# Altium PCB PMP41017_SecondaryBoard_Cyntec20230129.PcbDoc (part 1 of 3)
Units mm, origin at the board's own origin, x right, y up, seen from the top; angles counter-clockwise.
Board outline 56.93 x 50 mm, 6 copper layers (Top Layer, Layer 1, Layer 3, Layer 4, Layer 2, Bottom Layer), stack 1.219 mm thick; 147 components, 63 nets, 876 pads, 1174 vias.
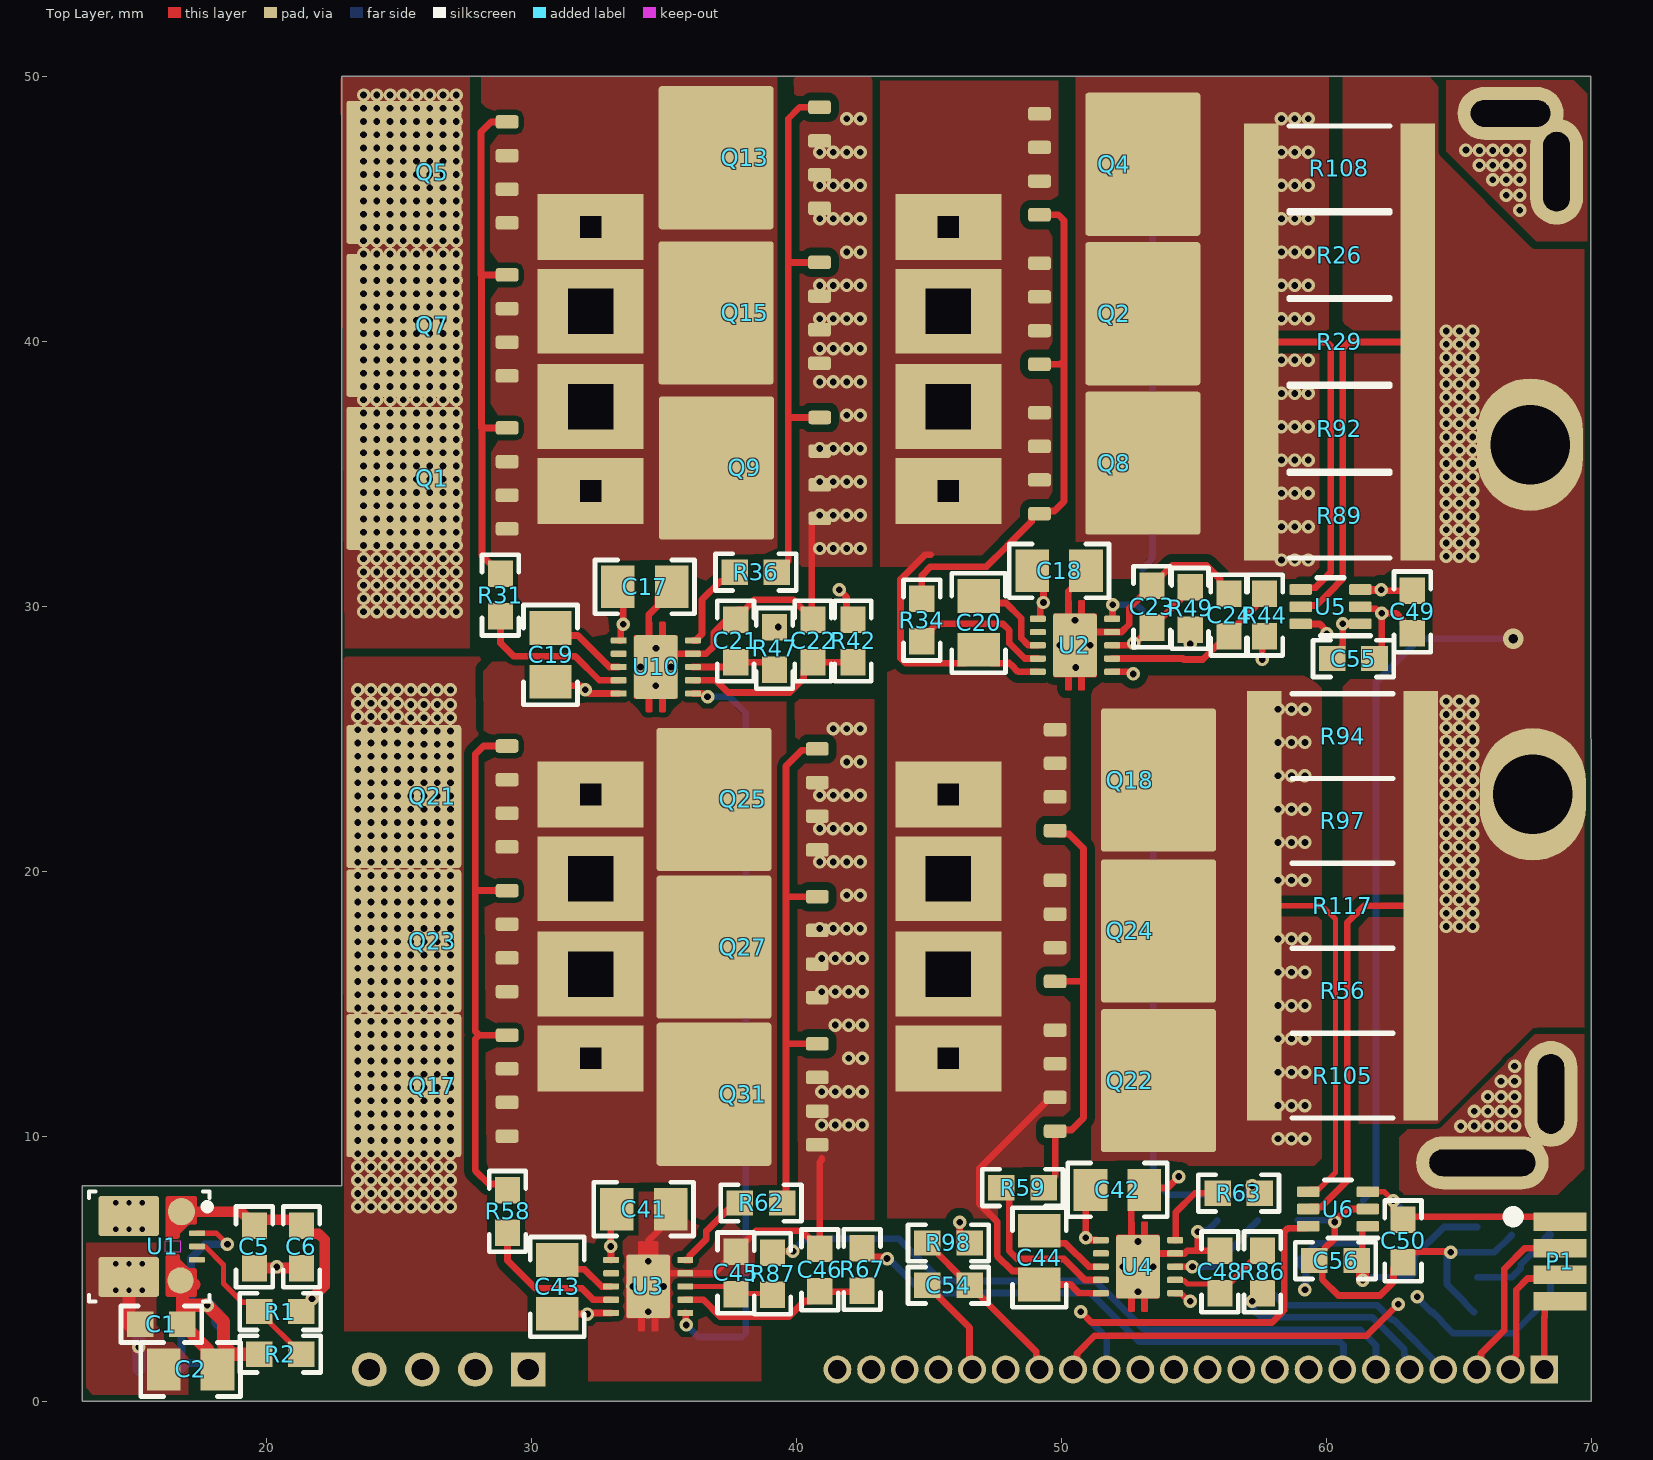
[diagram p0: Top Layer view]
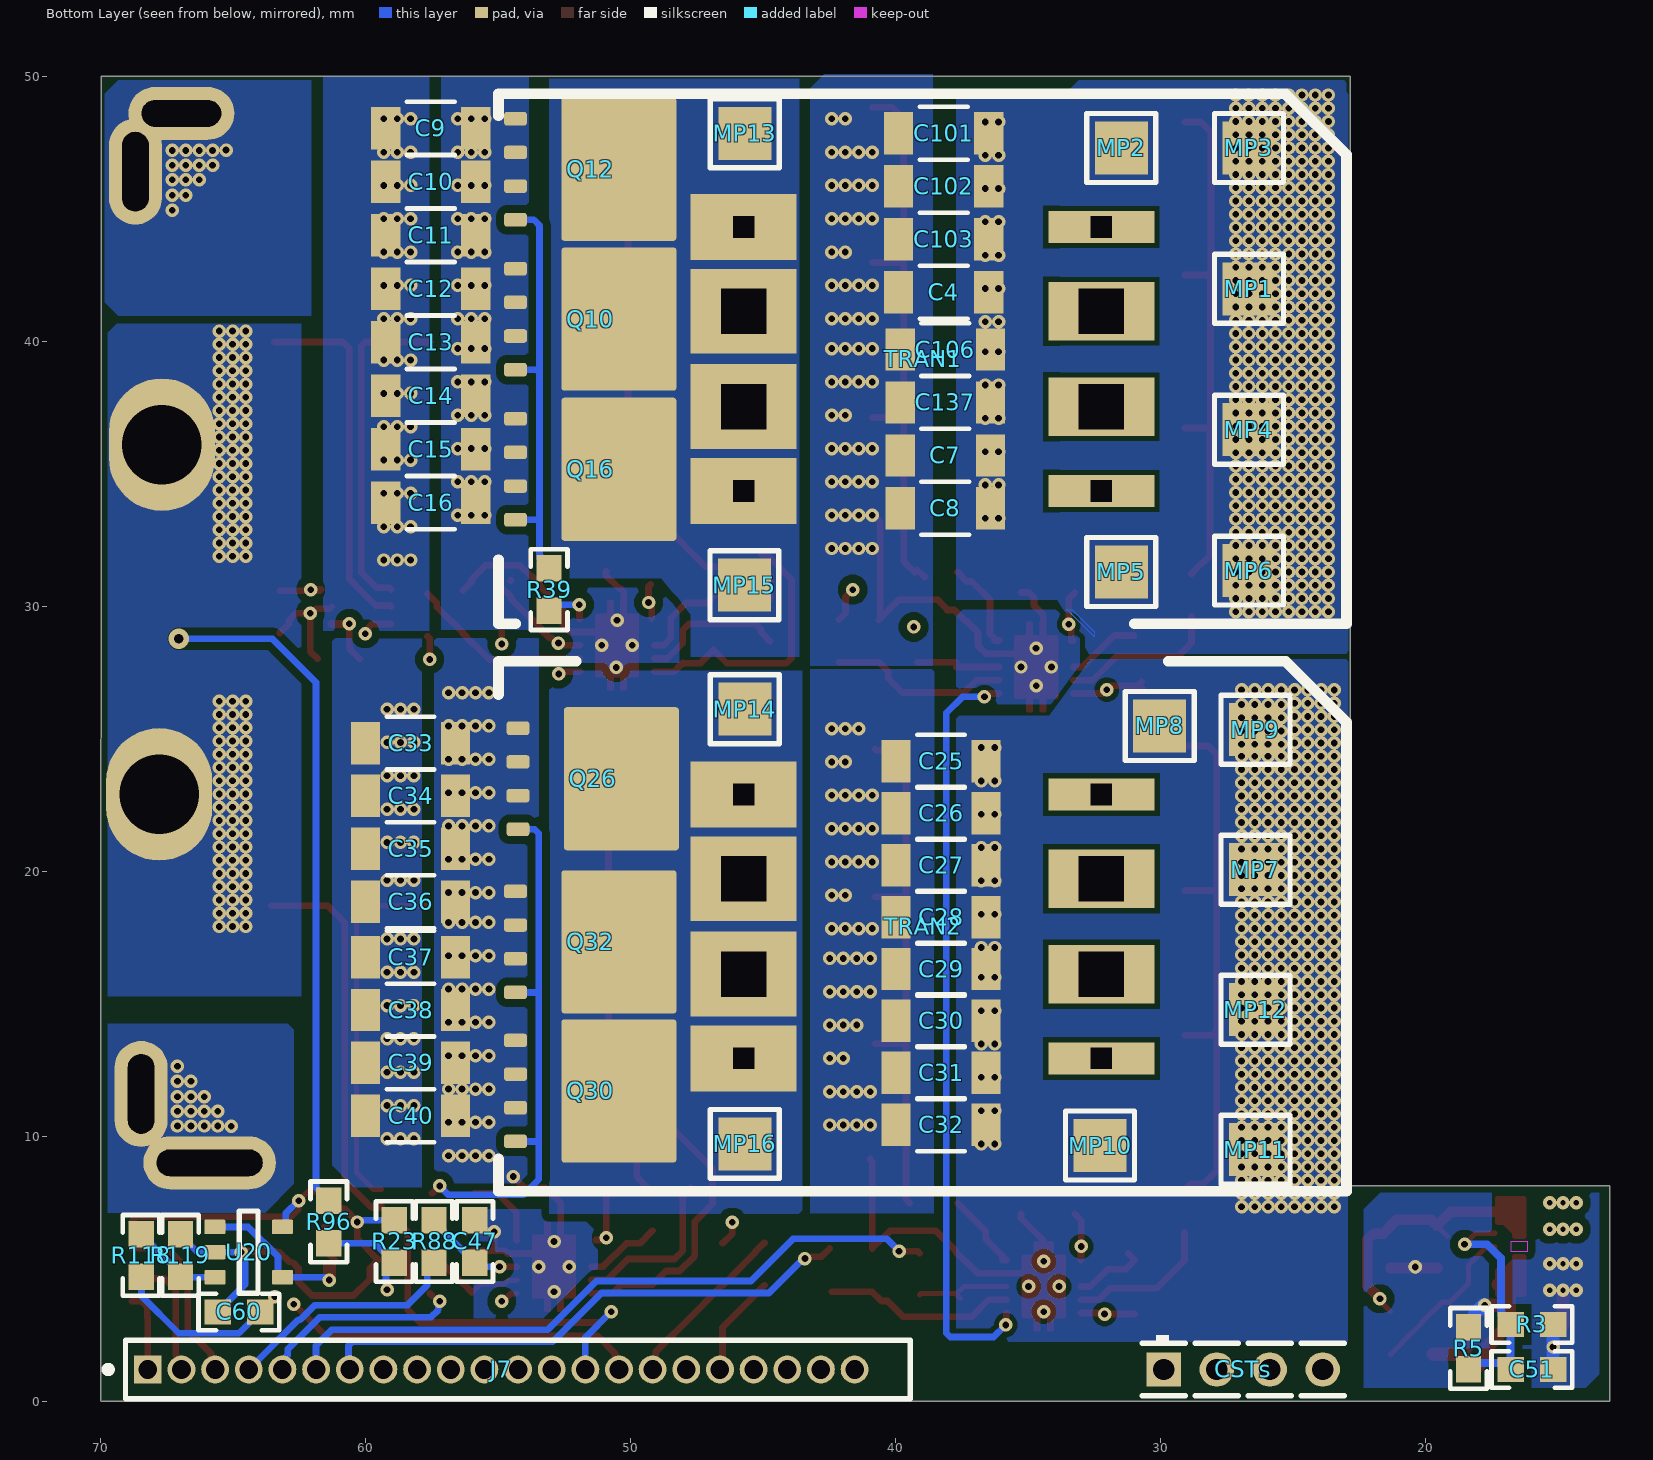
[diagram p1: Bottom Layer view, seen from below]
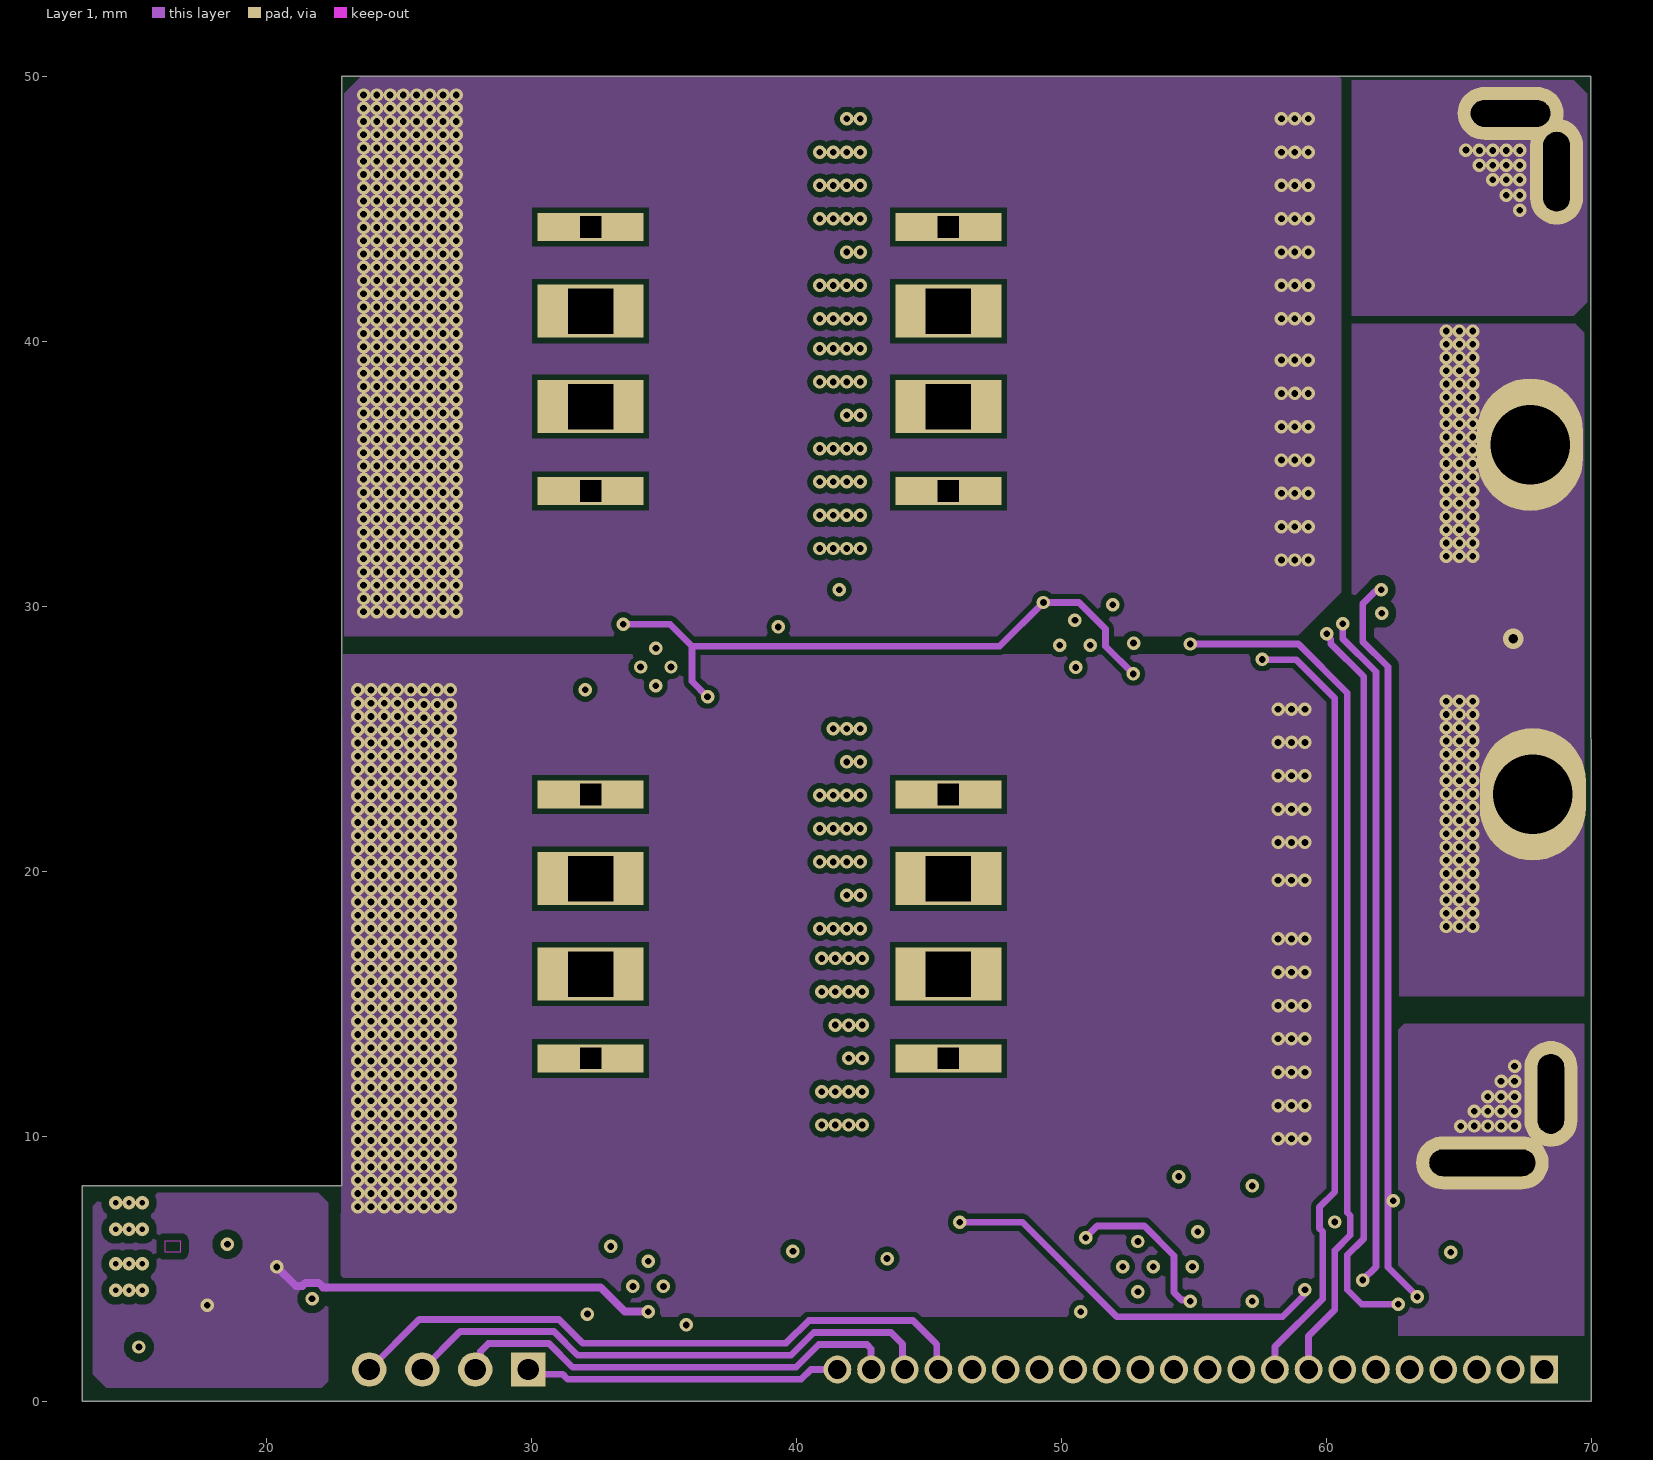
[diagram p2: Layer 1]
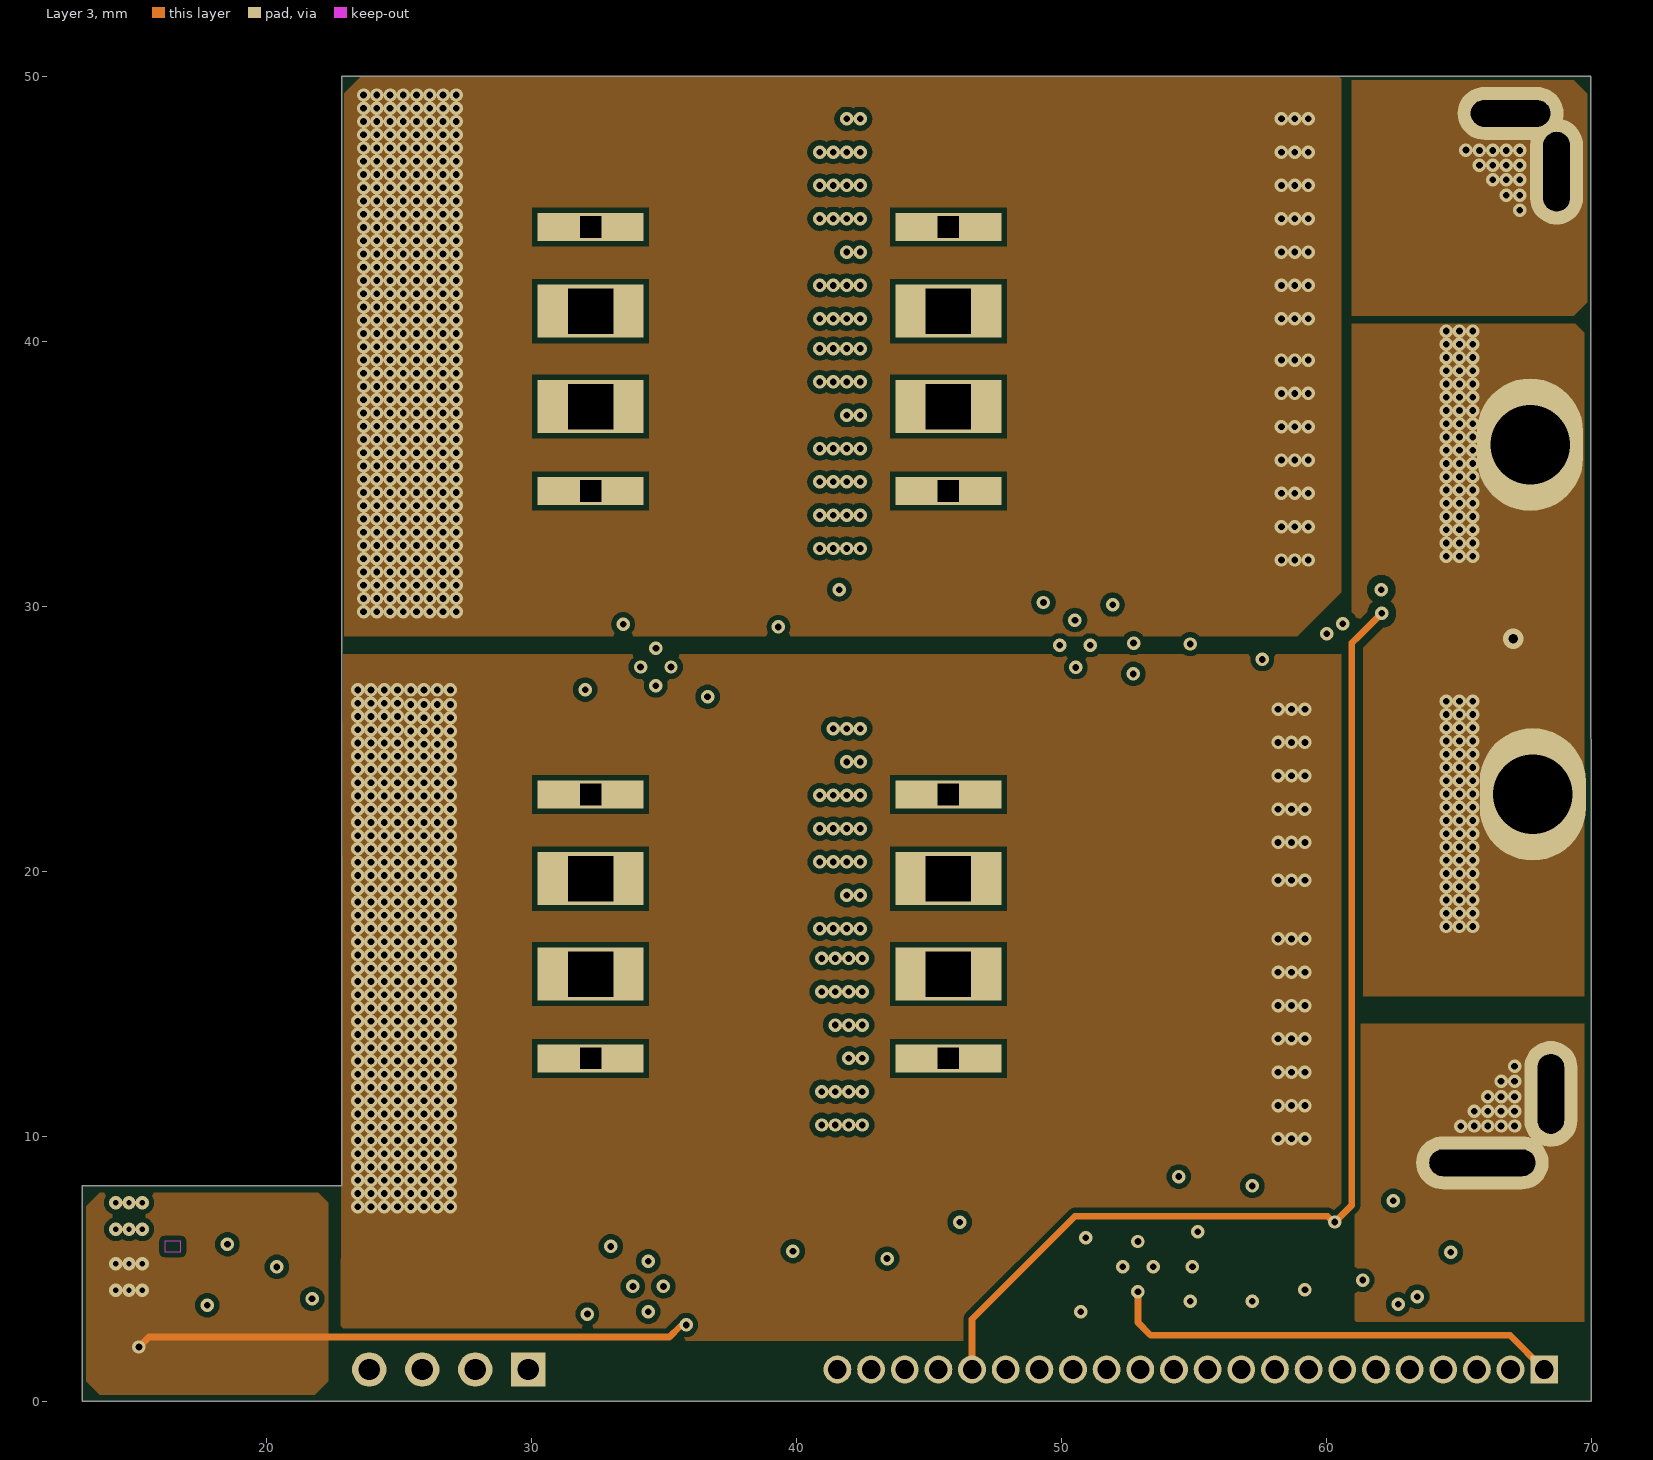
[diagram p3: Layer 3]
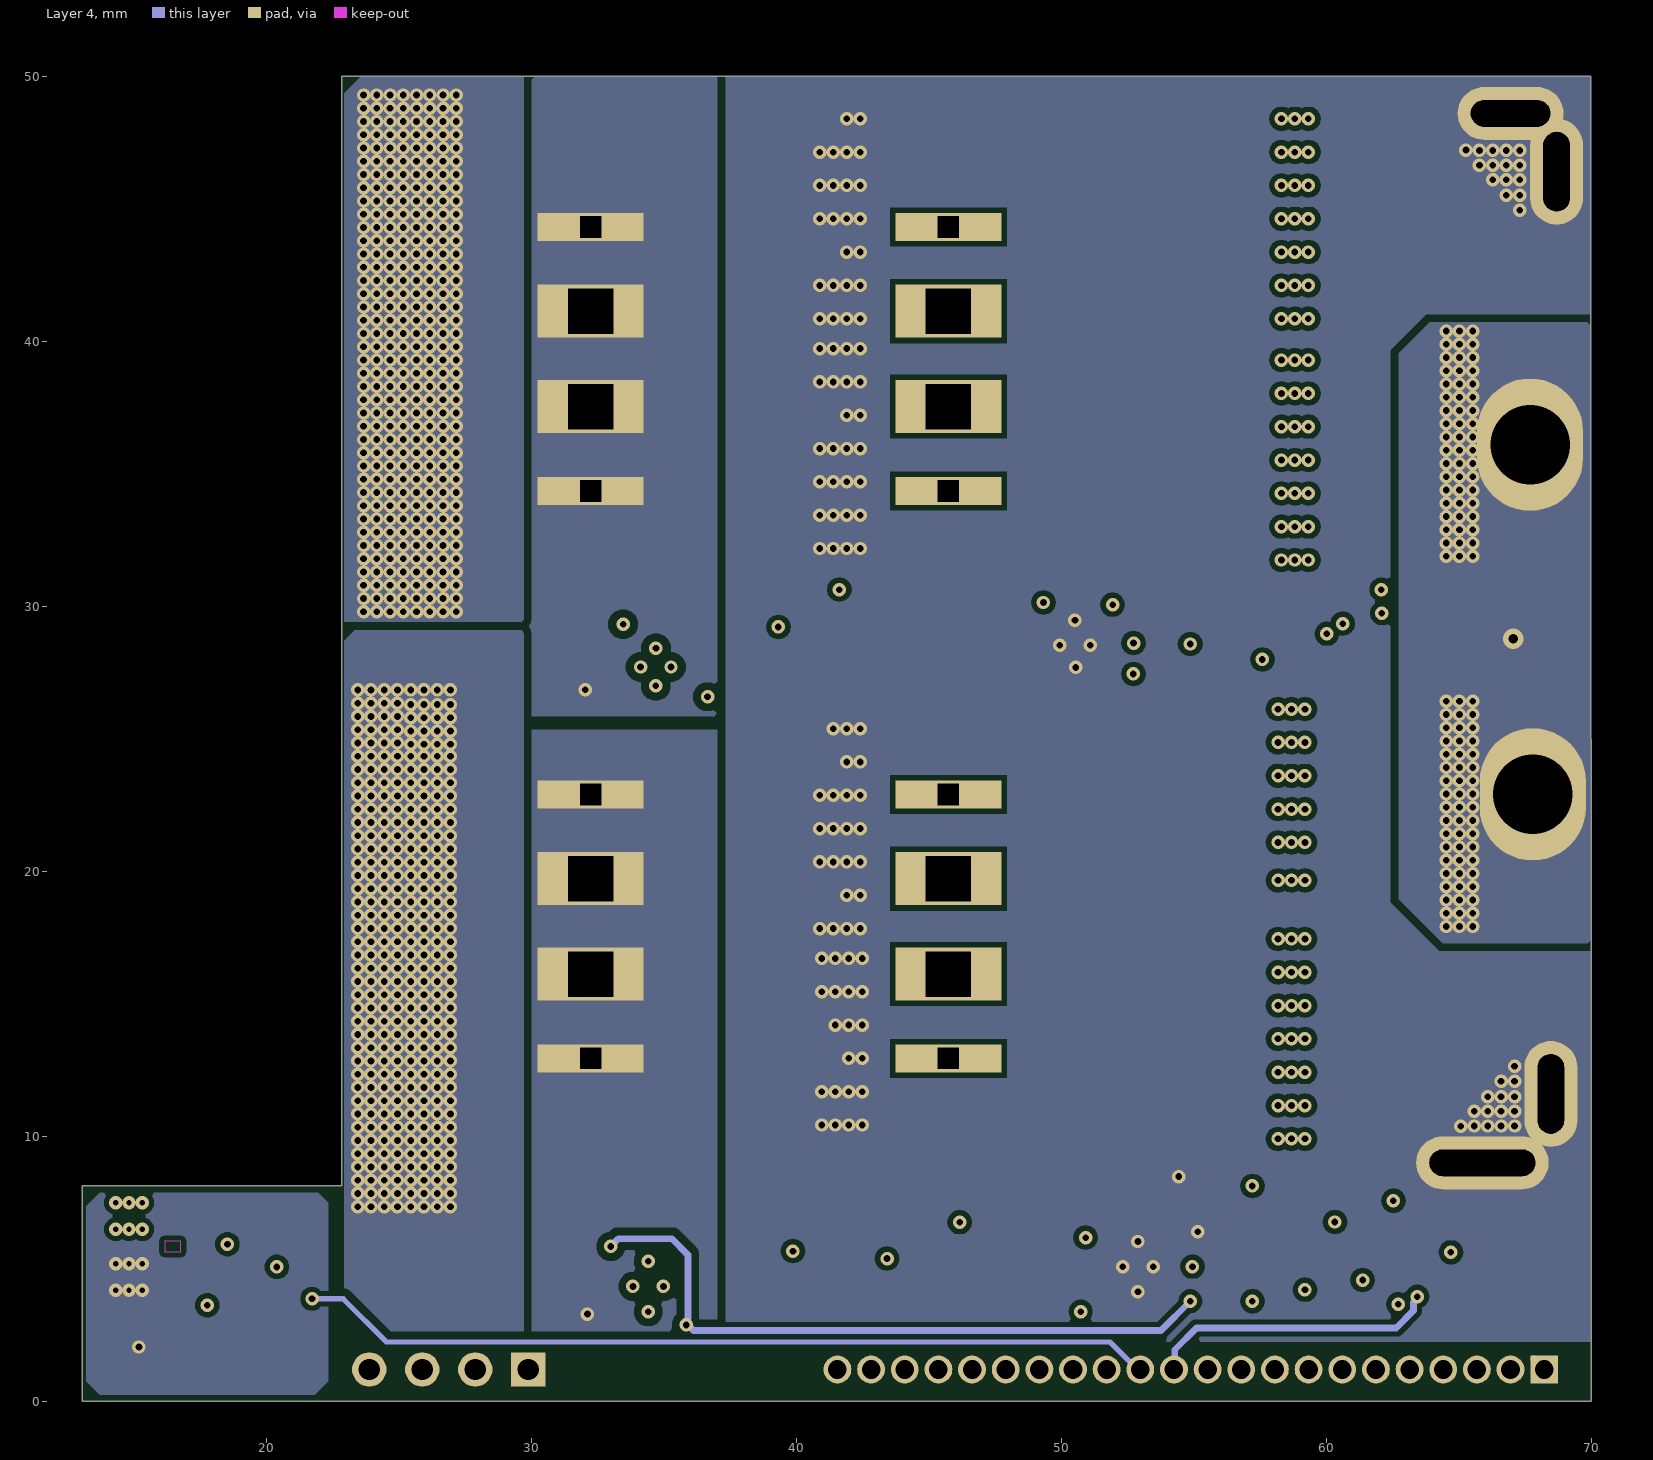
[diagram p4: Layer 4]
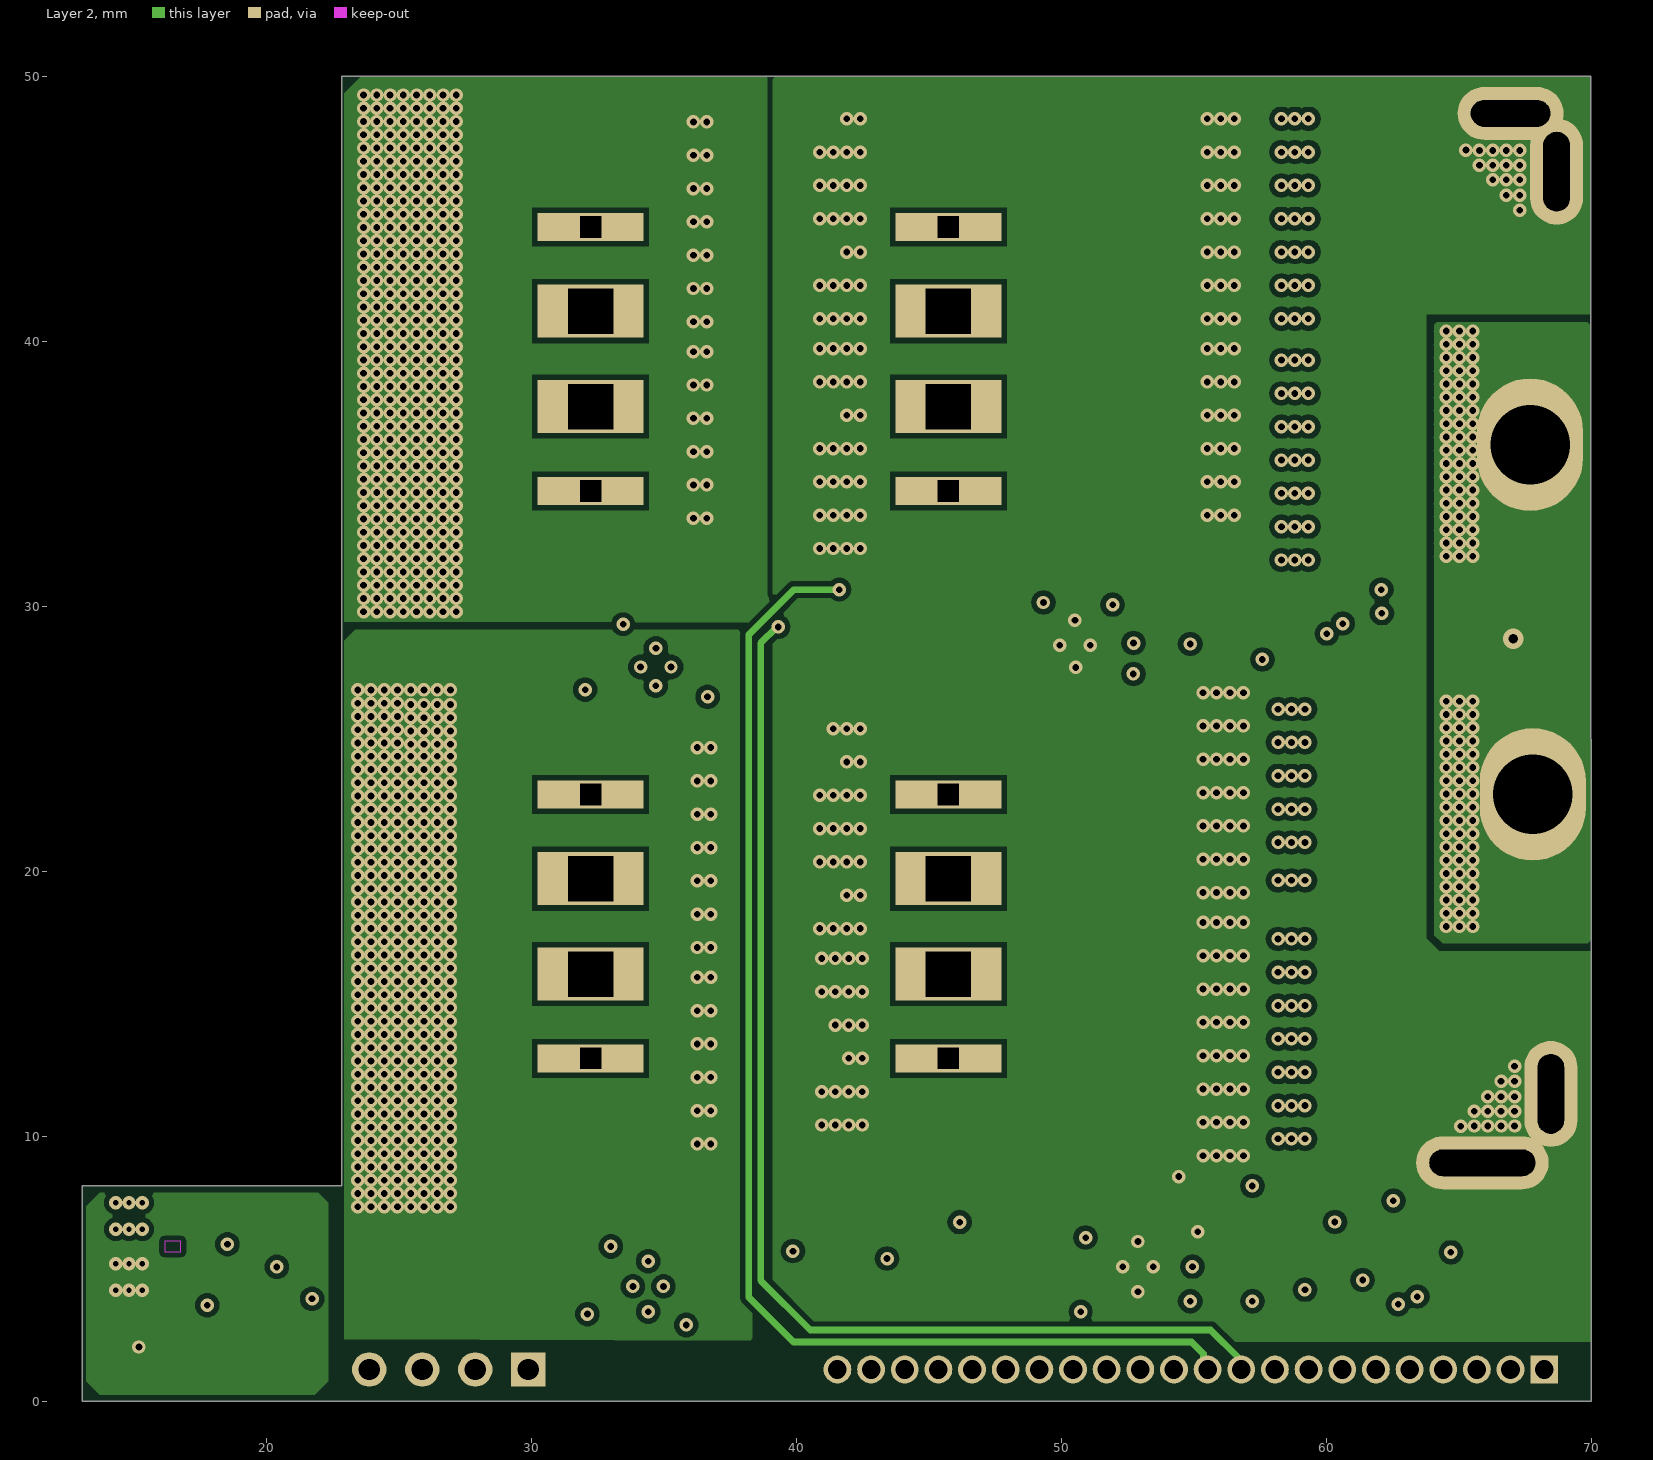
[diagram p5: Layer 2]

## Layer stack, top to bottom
Top Solder: solder mask 0.0102, Solder Resist, Dk 3.5
Top Layer: signal copper 0.105
Dielectric 1: core 0.0711, PP-006, Dk 4.1
Layer 1: signal copper 0.105
Dielectric 3: prepreg 0.0711, PP-006, Dk 4.1
Layer 3: signal copper 0.105
Dielectric1: core 0.3048, Core-030, Dk 4.3
Layer 4: signal copper 0.105
Dielectric 4: prepreg 0.0711, PP-006, Dk 4.1
Layer 2: signal copper 0.105
Dielectric 2: core 0.0711, PP-006, Dk 4.1
Bottom Layer: signal copper 0.105
Bottom Solder: solder mask 0.0102, Solder Resist, Dk 3.5

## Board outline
13.069,0 70,0 69.98,50 22.86,50 22.86,8.128 13.069,8.128

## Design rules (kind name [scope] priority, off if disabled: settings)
AcuteAngle [All] p1 off: minimum=4.50000000000000E+0001 checktracksonly=FALSE
AssemblyTestPointUsage [All] p1: valid=2
BoardOutlineClearance BoardOutlineClearance_MountingHoles [OnCopper and InComponentClass('Mounting Holes')] p1 off: gap=0.2 ignorepadtopadclearanceinfootprint=FALSE
BoardOutlineClearance BoardOutlineClearance_Poly [OnCopper and IsPoly] p2 off: gap=0.2 ignorepadtopadclearanceinfootprint=FALSE
BoardOutlineClearance [OnCopper and Not InComponentClass('Logo') and not InComponentClass('FiducialMark') and not InRegion(1000,500,4000,800) and not InPoly] p3 off: gap=0.2 ignorepadtopadclearanceinfootprint=FALSE
Clearance Clearance_Keepouts [((IsTrack Or IsArc) And Not InPoly) And IsFree and IsKeepOut vs ((IsTrack Or IsArc) And Not InPoly) And IsFree and IsKeepOut] p1: gap=0 ignorepadtopadclearanceinfootprint=FALSE
Clearance Clearance_Poly [InPolygon] p2: gap=0.2 ignorepadtopadclearanceinfootprint=TRUE
Clearance Clearance_FiducialMark [IsKeepOut and InComponentClass('FiducialMark') vs IsPad and InComponentClass('FiducialMark')] p3: gap=0 ignorepadtopadclearanceinfootprint=FALSE
Clearance [All] p4: gap=0.2 ignorepadtopadclearanceinfootprint=TRUE
ComponentClearance ComponentClearance_MountingHoles_FiducialMarks [InComponentClass('Mounting Holes') vs InComponentClass('FiducialMark')] p1 off: gap=1.27 collisioncheckmode=3 verticalgap=0.254 showdistances=FALSE
ComponentClearance ComponentClearance_Shunt [InComponentClass('Header') vs InComponentClass('Shunt')] p2 off: gap=0 collisioncheckmode=3 verticalgap=0 showdistances=FALSE
ComponentClearance ComponentClearance_Logo [InComponentClass('Logo')] p3 off: gap=0.762 collisioncheckmode=3 verticalgap=0.254 showdistances=FALSE
ComponentClearance ComponentClearance_ScrewToNut [(HasFootprint('NY PMS 440 0025 PH')) vs (HasFootprint('Keystone_1902C'))] p4 off: gap=0.127 collisioncheckmode=3 verticalgap=0.254 showdistances=FALSE
ComponentClearance ComponentClearance_MountingHoles [InComponentClass('Mounting Holes')] p5 off: gap=2.54 collisioncheckmode=3 verticalgap=2540 showdistances=FALSE
ComponentClearance ComponentClearance_SmallPassives [HasFootprint('0201*') or HasFootprint('0402*') or HasFootprint('0508') or HasFootprint('0603*') or HasFootprint('0612') or HasFootprint('0805*') or HasFootprint('0815*') or HasFootprint('0830*') or HasFootprint('1206*') or HasFootprint('1210*') or HasFootprint('1808*') or HasFootprint('1812*') or HasFootprint('1825*') or HasFootprint('2010*') or HasFootprint('2220*') or HasFootprint('2225*') or HasFootprint('2512*') or HasFootprint('2728*') or HasFootprint('3518*') vs HasFootprint('0201*') or HasFootprint('0402*') or HasFootprint('0508') or HasFootprint('0603*') or HasFootprint('0612') or HasFootprint('0805*') or HasFootprint('0815*') or HasFootprint('0830*') or HasFootprint('1206*') or HasFootprint('1210*') or HasFootprint('1808*') or HasFootprint('1812*') or HasFootprint('1825*') or HasFootprint('2010*') or HasFootprint('2220*') or HasFootprint('2225*') or HasFootprint('2512*') or HasFootprint('2728*') or HasFootprint('3518*')] p6 off: gap=0.38 collisioncheckmode=3 verticalgap=0.254 showdistances=FALSE
ComponentClearance ComponentClearance_THtoSMT [IsThruComponent vs IsSMTComponent] p7 off: gap=0.762 collisioncheckmode=3 verticalgap=0.762 showdistances=FALSE
ComponentClearance ComponentClearance_THtoTH [IsThruComponent vs IsThruComponent] p8 off: gap=0.508 collisioncheckmode=3 verticalgap=0.762 showdistances=FALSE
ComponentClearance [All] p9 off: gap=0.508 collisioncheckmode=3 verticalgap=0.254 showdistances=FALSE
DiffPairsRouting [All] p1: maxlimit=2.54 minlimit=0.254 mostfreqgap=0.254 toplayer_minwidth=0.381 toplayer_maxwidth=0.381 toplayer_prefwidth=0.381 midlayer1_minwidth=0.381 midlayer1_maxwidth=0.381 midlayer1_prefwidth=0.381 midlayer2_minwidth=0.381 midlayer2_maxwidth=0.381 midlayer2_prefwidth=0.381 midlayer3_minwidth=0.381 midlayer3_maxwidth=0.381 midlayer3_prefwidth=0.381 midlayer4_minwidth=0.381 midlayer4_maxwidth=0.381 midlayer4_prefwidth=0.381 bottomlayer_minwidth=0.381 bottomlayer_maxwidth=0.381 bottomlayer_prefwidth=0.381 maxuncoupledlength=25.4
FabricationTestPointUsage TestPointUsage [All] p1: valid=2 allowmultiple=FALSE
FabricationTestpoint Testpoint [All] p1: side=3 testpointundercomponent=TRUE minsize=1.016 maxsize=2.54 preferedsize=1.524 minholesize=0 maxholesize=1.016 preferedholesize=0.813 testpointgrid=0.025 allowsidetop=TRUE allowsidebottom=TRUE usegrid=TRUE gridtolerance=0
FanoutControl Fanout_LCC [IsLCC] p1: bgadir=Out bgaviamode=Centered fanoutstyle=Auto fanoutdirection=Alternating viagrid=0.025 // Fanout_LCC (Default Rule)
FanoutControl Fanout_BGA [IsBGA] p2: bgadir=Out bgaviamode=Centered fanoutstyle=Auto fanoutdirection=Alternating viagrid=0.025 // Fanout_BGA (Default Rule)
FanoutControl Fanout_Default [All] p4: bgadir=Out bgaviamode=Centered fanoutstyle=Auto fanoutdirection=Alternating viagrid=0.025 // Fanout_Default (Default Rule)
FanoutControl Fanout_Small [(CompPinCount < 5)] p5: bgadir=Out bgaviamode=Centered fanoutstyle=Auto fanoutdirection=OutThenIn viagrid=0.025 // Fanout_Small (Default Rule)
Height [All] p1 off: minheight=0 maxheight=30 prefheight=12.7
HoleSize [All] p1: absolutevalues=TRUE maxlimit=6.375 minlimit=0.2 maxpercent=80.000 minpercent=20.000
HoleToHoleClearance [All] p1: gap=0.2 allowstackedmicrovias=TRUE
MinimumAnnularRing MinimumAnnularRing_ThermalPadVias [IsVia and InAnyComponent] p1: minimumring=0.127
MinimumAnnularRing [All] p2: minimumring=0.12
MinimumSolderMaskSliver MinimumSolderMaskSliver_Logo [InComponentClass('Logo') vs InComponentClass('Logo')] p1: minsoldermaskwidth=0.018
MinimumSolderMaskSliver [All] p2: minsoldermaskwidth=0.1
PlaneConnect [All] p1: planeconnectstyle=Relief reliefexpansion=0.254 reliefentries=4 reliefconductorwidth=0.254 reliefairgap=0.254
PolygonConnect [All] p1: connectstyle=Direct reliefconductorwidth=0.254 reliefentries=4 polygonreliefangle="90 Angle" airgapwidth=0.254
RoutingVias ThermalPadVias [IsVia and InAnyComponent] p1: holewidth=0.2 width=0.5 viastyle="Through Hole" minholewidth=0.2 minwidth=0.5 maxholewidth=0.33 maxwidth=0.6
RoutingVias [All] p2: holewidth=0.3 width=0.508 viastyle="Through Hole" minholewidth=0.2 minwidth=0.5 maxholewidth=1.016 maxwidth=1.651
SilkToBoardRegionClearance [Not ((IsComment or IsDesignator) And (Hide <> 'False')) and not InRegion(1000,500,4000,800)] p1:
SilkToSilkClearance SilkToSilkClearance_Pb-FreeLogo [(HasFootprint('Pb-Free_Overlay_Medium') OR HasFootprint('Pb-Free_Overlay_Small')) vs (HasFootprint('Pb-Free_Overlay_Medium') OR HasFootprint('Pb-Free_Overlay_Small'))] p1: silktosilkclearance=0
SilkToSilkClearance [All] p2: silktosilkclearance=0.1
SilkToSolderMaskClearance SilkToComponentPadClearance [(IsPad or IsFill or IsRegion) and InAnycomponent] p1 off: minsilkscreentomaskgap=0.127 clearancetoexposedcopper=TRUE
SilkToSolderMaskClearance "Silk to Solder Mask Opening" [All] p2 off: minsilkscreentomaskgap=0.1 clearancetoexposedcopper=FALSE
SolderMaskExpansion [All] p1: expansion=0.05 istentingtop=FALSE
UnRoutedNet [All] p1: checkbadconnections=TRUE
Width [All] p1: maxlimit=2.54 minlimit=0.152 preferedwidth=0.254
12 further rules are at their usual default settings.

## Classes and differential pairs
component class Header: CSTs

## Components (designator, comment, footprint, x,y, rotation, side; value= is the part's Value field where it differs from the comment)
C1 "C0603C104K5RACTU" 0603 16.046,2.906 r0 top value=0.1uF
C2 "GRM21BC81C226ME44L" 0805_HV 17.153,1.2 r0 top value=22uF
C4 "GMK316AB7106KL-TR" 1206_190 38.198,41.851 r0 bottom value=10uF
C5 "C1608X5R1E106M080AC" 0603 19.558,5.828 r270 top value=10uF
C6 "C0603C104K5RACTU" 0603 21.336,5.828 r270 top value=0.1uF
C7 "GMK316AB7106KL-TR" 1206_190 38.138,35.691 r0 bottom value=10uF
C8 "GMK316AB7106KL-TR" 1206_190 38.138,33.693 r0 bottom value=10uF
C9 "GMK316AB7106KL-TR" 1206_190 57.554,48.031 r180 bottom value=10uF
C10 "GMK316AB7106KL-TR" 1206_190 57.554,46.014 r180 bottom value=10uF
C11 "GMK316AB7106KL-TR" 1206_190 57.554,43.996 r180 bottom value=10uF
C12 "GMK316AB7106KL-TR" 1206_190 57.554,41.978 r180 bottom value=10uF
C13 "GMK316AB7106KL-TR" 1206_190 57.554,39.961 r180 bottom value=10uF
C14 "GMK316AB7106KL-TR" 1206_190 57.554,37.943 r180 bottom value=10uF
C15 "GMK316AB7106KL-TR" 1206_190 57.554,35.926 r180 bottom value=10uF
C16 "GMK316AB7106KL-TR" 1206_190 57.554,33.908 r180 bottom value=10uF
C17 "C2012X7R1V475K125AC" 0805_HV 34.29,30.734 r0 top value=4.7uF
C18 "C2012X7R1V475K125AC" 0805_HV 49.928,31.334 r0 top value=4.7uF
C19 "C2012X7R1V475K125AC" 0805_HV 30.734,28.166 r270 top value=4.7uF
C20 "C2012X7R1V475K125AC" 0805_HV 46.889,29.371 r270 top value=4.7uF
C21 "CGA3E2C0G1H101J080AA" 0603 37.722,28.69 r270 top value=100pF
C22 "CGA3E2C0G1H101J080AA" 0603 40.639,28.69 r270 top value=100pF
C23 "CGA3E2C0G1H101J080AA" 0603 53.428,29.982 r270 top value=100pF
C24 "CGA3E2C0G1H101J080AA" 0603 56.342,29.67 r270 top value=100pF
C25 "GMK316AB7106KL-TR" 1206_190 38.298,24.146 r0 bottom value=10uF
C26 "GMK316AB7106KL-TR" 1206_190 38.298,22.188 r0 bottom value=10uF
C27 "GMK316AB7106KL-TR" 1206_190 38.298,20.229 r0 bottom value=10uF
C28 "GMK316AB7106KL-TR" 1206_190 38.298,18.27 r0 bottom value=10uF
C29 "GMK316AB7106KL-TR" 1206_190 38.298,16.312 r0 bottom value=10uF
C30 "GMK316AB7106KL-TR" 1206_190 38.298,14.353 r0 bottom value=10uF
C31 "GMK316AB7106KL-TR" 1206_190 38.298,12.395 r0 bottom value=10uF
C32 "GMK316AB7106KL-TR" 1206_190 38.298,10.436 r0 bottom value=10uF
C33 "GMK316AB7106KL-TR" 1206_190 58.318,24.838 r180 bottom value=10uF
C34 "GMK316AB7106KL-TR" 1206_190 58.318,22.844 r180 bottom value=10uF
C35 "GMK316AB7106KL-TR" 1206_190 58.318,20.851 r180 bottom value=10uF
C36 "GMK316AB7106KL-TR" 1206_190 58.318,18.857 r180 bottom value=10uF
C37 "GMK316AB7106KL-TR" 1206_190 58.318,16.759 r180 bottom value=10uF
C38 "GMK316AB7106KL-TR" 1206_190 58.318,14.765 r180 bottom value=10uF
C39 "GMK316AB7106KL-TR" 1206_190 58.318,12.772 r180 bottom value=10uF
C40 "GMK316AB7106KL-TR" 1206_190 58.318,10.778 r180 bottom value=10uF
C41 "C2012X7R1V475K125AC" 0805_HV 34.25,7.25 r0 top value=4.7uF
C42 "C2012X7R1V475K125AC" 0805_HV 52.127,7.975 r0 top value=4.7uF
C43 "C2012X7R1V475K125AC" 0805_HV 30.988,4.318 r270 top value=4.7uF
C44 "C2012X7R1V475K125AC" 0805_HV 49.18,5.423 r270 top value=4.7uF
C45 "CGA3E2C0G1H101J080AA" 0603 37.728,4.842 r270 top value=100pF
C46 "CGA3E2C0G1H101J080AA" 0603 40.894,4.956 r270 top value=100pF
C47 "CGA3E2C0G1H101J080AA" 0603 55.895,6.03 r270 bottom value=100pF
C48 "CGA3E2C0G1H101J080AA" 0603 55.994,4.882 r270 top value=100pF
C49 "C1608X7R1E104K080AA" 0603 63.255,29.79 r270 top value=0.1uF
C50 "C1608X7R1E104K080AA" 0603 62.907,6.05 r270 top value=0.1uF
C51 "GRM1885C2A330JA01D" 0603 16.002,1.2 r0 bottom value=33pF
C54 "C0603C471K5RACTU" 0603 45.747,4.379 r180 top value=470pF
C55 "C1608X7R1E104K080AA" 0603 61.027,28.025 r180 top value=0.1uF
C56 "C1608X7R1E104K080AA" 0603 60.356,5.307 r0 top value=0.1uF
C60 "C1608X7R1E104K080AA" 0603 64.793,3.371 r180 bottom value=0.1uF
C101 "GMK316AB7106KL-TR" 1206_190 38.198,47.847 r0 bottom value=10uF
C102 "GMK316AB7106KL-TR" 1206_190 38.198,45.849 r0 bottom value=10uF
C103 "GMK316AB7106KL-TR" 1206_190 38.198,43.85 r0 bottom value=10uF
C106 "GMK316AB7106KL-TR" 1206_190 38.138,39.689 r0 bottom value=10uF
C137 "GMK316AB7106KL-TR" 1206_190 38.138,37.69 r0 bottom value=10uF
CSTs "PTT-104-01-L-S" Samtec_PTT-104-01-x-S 26.894,1.2 r180 bottom
J7 "M52-5002345" M52-5012345 68.23,1.2 r180 bottom locked
MP1 "2mmx2mm copper" "Copper 2x2" 26.678,41.978 r180 bottom
MP2 "2mmx2mm copper" "Copper 2x2" 31.496,47.294 r180 bottom
MP3 "2mmx2mm copper" "Copper 2x2" 26.678,47.294 r180 bottom
MP4 "2mmx2mm copper" "Copper 2x2" 26.678,36.663 r180 bottom
MP5 "2mmx2mm copper" "Copper 2x2" 31.496,31.294 r180 bottom
MP6 "2mmx2mm copper" "Copper 2x2" 26.678,31.348 r180 bottom
MP7 "2mmx2mm copper" "Copper 2x2" 26.432,20.06 r180 bottom
MP8 "2mmx2mm copper" "Copper 2x2" 30.047,25.483 r180 bottom
MP9 "2mmx2mm copper" "Copper 2x2" 26.432,25.343 r180 bottom
MP10 "2mmx2mm copper" "Copper 2x2" 32.298,9.652 r180 bottom
MP11 "2mmx2mm copper" "Copper 2x2" 26.432,9.496 r180 bottom
MP12 "2mmx2mm copper" "Copper 2x2" 26.432,14.778 r180 bottom
MP13 "2mmx2mm copper" "Copper 2x2" 45.704,47.847 r180 bottom
MP14 "2mmx2mm copper" "Copper 2x2" 45.704,26.118 r180 bottom
MP15 "2mmx2mm copper" "Copper 2x2" 45.719,30.794 r180 bottom
MP16 "2mmx2mm copper" "Copper 2x2" 45.704,9.711 r180 bottom
P1 "EDGE_CONN_503480-0400" JAE_EDGE_CONN_503480-0400 68.834,5.28 r270 top
Q1 "CSD17573Q5B" DNK0008A#1 26.276,34.826 r180 top value=30V
Q2 "CSD17573Q5B" DNK0008A#1 52.006,41.04 r0 top value=30V
Q4 "CSD17573Q5B" DNK0008A#1 52.006,46.68 r0 top value=30V
Q5 "CSD17573Q5B" DNK0008A#1 26.276,46.373 r180 top value=30V
Q7 "CSD17573Q5B" DNK0008A#1 26.276,40.6 r180 top value=30V
Q8 "CSD17573Q5B" DNK0008A#1 52.006,35.401 r0 top value=30V
Q9 "CSD17573Q5B" DNK0008A#1 38.073,35.219 r180 top value=30V
Q10 "CSD17573Q5B" DNK0008A#2 51.535,40.834 r180 bottom value=30V
Q12 "CSD17573Q5B" DNK0008A#2 51.536,46.49 r180 bottom value=30V
Q13 "CSD17573Q5B" DNK0008A#1 38.063,46.925 r180 top value=30V
Q15 "CSD17573Q5B" DNK0008A#1 38.063,41.072 r180 top value=30V
Q16 "CSD17573Q5B" DNK0008A#2 51.535,35.171 r180 bottom value=30V
Q17 "CSD17573Q5B" DNK0008A#1 26.276,11.911 r180 top value=30V
Q18 "CSD17573Q5B" DNK0008A#1 52.596,23.442 r0 top value=30V
Q21 "CSD17573Q5B" DNK0008A#1 26.276,22.823 r180 top value=30V
Q22 "CSD17573Q5B" DNK0008A#1 52.596,12.102 r0 top value=30V
Q23 "CSD17573Q5B" DNK0008A#1 26.276,17.367 r180 top value=30V
Q24 "CSD17573Q5B" DNK0008A#1 52.596,17.752 r0 top value=30V
Q25 "CSD17573Q5B" DNK0008A#1 37.981,22.712 r180 top value=30V
Q26 "CSD17573Q5B" DNK0008A#2 51.44,23.491 r180 bottom value=30V
Q27 "CSD17573Q5B" DNK0008A#1 37.981,17.136 r180 top value=30V
Q30 "CSD17573Q5B" DNK0008A#2 51.535,11.712 r180 bottom value=30V
Q31 "CSD17573Q5B" DNK0008A#1 37.981,11.586 r180 top value=30V
Q32 "CSD17573Q5B" DNK0008A#2 51.535,17.335 r180 bottom value=30V
R1 "CRCW060330K0JNEA" 0603 20.536,3.384 r180 top value=30k
R2 "CRCW060320K0JNEA" 0603 20.536,1.778 r180 top value=20k
R3 "RC0603FR-07220KL" 0603 16.002,2.899 r180 bottom value=220k
R5 "15K 0603" 0603 18.392,2 r270 bottom value=15.0k
R23 "RC0603FR-075K1L" 0603 58.928,6.03 r270 bottom value=5.10k
R26 "CSNL2512FTL500" 2512 60.503,43.248 r180 top value=0.0005
R29 "CSNL2512FTL500" 2512 60.503,39.973 r180 top value=0.0005
R31 "ERJ-3RQF2R2V" 0603 28.845,30.419 r90 top value=1.0
R34 "ERJ-3RQF2R2V" 0603 44.745,29.477 r90 top value=1.0
R36 "ERJ-3RQF2R2V" 0603 38.48,31.287 r0 top value=1.0
R39 "ERJ-3RQF2R2V" 0603 53.086,30.629 r90 bottom value=1.0
R42 "RC0603FR-07100RL" 0603 42.15,28.69 r270 top value=100
R44 "RC0603FR-07100RL" 0603 57.675,29.67 r90 top value=100
R47 "RC0603FR-07100RL" 0603 39.186,28.41 r270 top value=100
R49 "RC0603FR-07100RL" 0603 54.874,29.919 r90 top value=100
R56 "CSNL2512FTL500" 2512 60.625,15.494 r180 top value=0.0005
R58 "ERJ-3RQF2R2V" 0603 29.111,7.168 r90 top value=1.0
R59 "ERJ-3RQF2R2V" 0603 48.547,8.059 r0 top value=1.0
R62 "ERJ-3RQF1R0V" 0603 38.683,7.484 r0 top value=1.0
R63 "ERJ-3RQF1R0V" 0603 56.703,7.851 r0 top value=1.0
R67 "RC0603FR-07100RL" 0603 42.493,4.974 r270 top value=100
R86 "RC0603FR-07100RL" 0603 57.596,4.882 r90 top value=100
R87 "RC0603FR-07100RL" 0603 39.112,4.812 r270 top value=100
R88 "RC0603FR-07100RL" 0603 57.427,6.03 r90 bottom value=100
R89 "CSNL2512FTL500" 2512 60.503,33.422 r180 top value=0.0005
R92 "CSNL2512FTL500" 2512 60.503,36.697 r180 top value=0.0005
R94 "CSNL2512FTL500" 2512 60.625,25.102 r180 top value=0.0005
R96 "RC0603FR-0720KL" 0603 61.403,6.767 r270 bottom value=20.0k
R97 "CSNL2512FTL500" 2512 60.625,21.899 r180 top value=0.0005
R98 "RC0603FR-07100RL" 0603 45.747,5.975 r180 top value=100
R105 "CSNL2512FTL500" 2512 60.625,12.291 r180 top value=0.0005
R108 "CSNL2512FTL500" 2512 60.503,46.524 r180 top value=0.0005
R117 "CSNL2512FTL500" 2512 60.625,18.696 r180 top value=0.0005
R118 "RC0603FR-075K1L" 0603 68.481,5.503 r270 bottom value=5.10k
R119 "RC0603FR-07100RL" 0603 67.001,5.503 r270 bottom value=100
TRAN1 "PQ32" 86H-22072 38.997,39.333 r180 bottom locked
TRAN2 "PQ32" 86H-22072 38.997,17.92 r180 bottom
U1 "TPSM863252RDX" RDX0007A-MFG 15.494,5.842 r270 top
U2 "UCC27282DRCR" DRC0010J 50.525,28.527 r0 top
U3 "UCC27282DRCR" DRC0010J 34.42,4.334 r0 top
U4 "UCC27282DRCR" DRC0010J 52.902,5.08 r0 top
U5 "INA210BIDCKR" DCK0006A_N 60.168,29.984 r180 top
U6 "INA210BIDCKR" DCK0006A_N 60.451,7.255 r180 top
U10 "UCC27282DRCR" DRC0010J 34.706,27.709 r0 top
U20 "TS321IDBVR" DBV0005A_L 64.425,5.629 r180 bottom

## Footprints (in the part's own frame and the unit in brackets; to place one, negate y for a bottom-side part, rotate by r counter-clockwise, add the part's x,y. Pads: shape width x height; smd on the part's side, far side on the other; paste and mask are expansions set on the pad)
86H-22072 [mm] "1.6kW 386V to 12V"
  rect 4x1.2 / inner rect 4x1.05 / far side rect 4x2.5 hole 0.8 square: 1(6.75,4.98) 1e(6.75,-4.98)
  rect 4x2.2 / inner rect 4x2 / far side rect 4x3.2 hole 1.7 square: 1ab(6.75,1.8) 1cd(6.75,-1.8)
  rect 4x2.5 / inner rect 4x1.05 / far side rect 4x2.5 hole 0.8 square: 2(-6.75,4.98) 2e(-6.75,-4.98)
  rect 4x3.2 / inner rect 4x2 / far side rect 4x3.2 hole 1.7 square: 2ab(-6.75,1.8) 2cd(-6.75,-1.8)
  silkscreen extent -16,-10 16,10
0603 [mm] "0603 from SM-752 data"
  rect 1x0.95 smd: 1(-0.8,0) 2(0.8,0)
  silkscreen extent -1.52,-0.69 1.52,0.69, body extent -0.87,-0.47 0.87,0.47, height 1
0805_HV [mil] "0805 with 30mil clearance between pads"
  rect 50x63 smd: 1(-40,0) 2(40,0)
  silkscreen extent -74,-40 74,40, body extent -43,-29 43,29, height 57
1206_190 [mm] "1206_190"
  rect 1.1x1.6 smd: 1(-1.7,0) 2(1.7,0)
  silkscreen extent -0.9,-1 0.9,1, body extent -1.75,-0.95 1.75,0.95, height 1.9
2512 [mm] "Chip Resistor, Body 6.3x3.2mm, IPC Medium Density"
  rect 1.3x3.4 smd: 1(-2.95,0) 2(2.95,0)
  silkscreen extent -1.9,-1.6 1.9,1.6, body extent -3.22,-1.67 3.22,1.67, height 0.71
"Copper 2x2" [mm] "copper 2mmx2mmx2mm"
  rect 2x2 smd: 1(0,0)
  silkscreen extent -1.3,-1.3 1.3,1.3
DBV0005A_L [mm] "SOT23, 5-Leads, Body 2.9x1.6mm, Pitch 0.95mm, Lead Span 2.8mm, IPC High Density"
  rrect18% 0.8x0.55 smd: 1(-1.275,0.95) 2(-1.275,0) 3(-1.275,-0.95) 4(1.275,-0.95) 5(1.275,0.95)
  silkscreen extent -0.35,-1.55 0.35,1.55, body extent -1.42,-1.46 1.42,1.46, height 1.09
DCK0006A_N [mm] "SOT23, 6-Leads, Body 2x1.3mm, Pitch 0.65mm, Lead Span 2.1mm, IPC Medium Density"
  rrect25% 0.85x0.4 smd: 1(-1.125,0.65) 2(-1.125,0) 3(-1.125,-0.65) 4(1.125,-0.65) 5(1.125,0) 6(1.125,0.65)
  silkscreen extent -1.5,-1.09 0.51,1.09, body extent -1.14,-1 1.14,1, height 0.95
DNK0008A#1 [mm] "SON, 8-Leads, Body 5x6mm"
  rrect39% 0.86x0.51 smd paste-0.05 mask-0.05: 1(-2.82,1.905) 2(-2.82,0.635) 3(-2.82,-0.635) 4(-2.82,-1.905) 5(2.82,-1.905) 6(2.82,-0.635) 7(2.82,0.635) 8(2.82,1.905)
  rrect40% 0.25x0.555 on Top Paste: 9(-0.83,2.372) 9(-0.83,-2.372)
  rrect40% 0.25x0.555 on Top Solder: 9(-0.83,2.372) 9(-0.83,-2.372)
  rrect11% 0.95x1.13 on Top Paste: 9(-0.535,1.33) 9(-0.535,0) 9(-0.535,-1.33) 9(0.615,1.33) 9(0.615,0) 9(0.615,-1.33) 9(1.765,-1.33) 9(1.765,0) 9(1.765,1.33)
  rrect3% 3.58x4 on Top Solder: 9(0.75,0)
  rrect5% 4.34x5.4 smd paste-3 mask-3: 9(1.08,0)
  body extent -3.05,-2.55 3.05,2.55, height 1.06
DNK0008A#2 [mm] "SON, 8-Leads, Body 5x6mm"
  rrect39% 0.86x0.51 smd paste-0.05 mask-0.05: 1(-2.82,1.905) 2(-2.82,0.635) 3(-2.82,-0.635) 4(-2.82,-1.905) 5(2.82,-1.905) 6(2.82,-0.635) 7(2.82,0.635) 8(2.82,1.905)
  rrect40% 0.25x0.555 on Bottom Paste: 9(-0.83,-2.372) 9(-0.83,2.372)
  rrect40% 0.25x0.555 on Bottom Solder: 9(-0.83,-2.372) 9(-0.83,2.372)
  rrect11% 0.95x1.13 on Bottom Paste: 9(-0.535,-1.33) 9(-0.535,0) 9(-0.535,1.33) 9(0.615,-1.33) 9(0.615,0) 9(0.615,1.33) 9(1.765,-1.33) 9(1.765,0) 9(1.765,1.33)
  rrect3% 3.58x4 on Bottom Solder: 9(0.75,0)
  rrect5% 4.34x5.4 smd paste-3 mask-3: 9(1.08,0)
  body extent -3.05,-2.55 3.05,2.55, height 1.06
DRC0010J [mm] "VSON-10"
  rrect42% 0.6x0.24 smd: 1(-1.4,1) 2(-1.4,0.5) 3(-1.4,0) 4(-1.4,-0.5) 5(-1.4,-1) 6(1.4,-1) 7(1.4,-0.5) 8(1.4,0) 9(1.4,0.5) 10(1.4,1)
  rrect12% 1.65x2.4 smd paste-1 mask-2: 11(0,0)
  Top Layer region: -0.375,-1.65 -0.375,-1.2 -0.775,-1.2 -0.794,-1.196 -0.81,-1.185 -0.821,-1.169 -0.825,-1.15 -0.825,-1.15 -0.825,1.15 -0.821,1.169 -0.81,1.185 -0.794,1.196 -0.775,1.2 -0.775,1.2 -0.375,1.2 -0.375,1.65 -0.371,1.669 -0.36,1.685 -0.344,1.696 -0.325,1.7 -0.325,1.7 -0.325,1.7 -0.175,1.7 -0.175,1.7 -0.156,1.696 -0.14,1.685 -0.129,1.669 -0.125,1.65 -0.125,1.65 -0.125,1.2 0.125,1.2 0.125,1.65 0.129,1.669 0.14,1.685 0.156,1.696 0.175,1.7 0.175,1.7 0.175,1.7 0.325,1.7 0.325,1.7 0.344,1.696 0.36,1.685 0.371,1.669 0.375,1.65 0.375,1.65 0.375,1.2 0.775,1.2 0.794,1.196 0.81,1.185 0.821,1.169 0.825,1.15 0.825,1.15 0.825,-1.15 0.821,-1.169 0.81,-1.185 0.794,-1.196 0.775,-1.2 0.775,-1.2 0.375,-1.2 0.375,-1.65 0.371,-1.669 0.36,-1.685 0.344,-1.696 0.325,-1.7 0.325,-1.7 0.175,-1.7 0.156,-1.696 0.14,-1.685 0.129,-1.669 0.125,-1.65 0.125,-1.65 0.125,-1.2 -0.125,-1.2 -0.125,-1.65 -0.129,-1.669 -0.14,-1.685 -0.156,-1.696 -0.175,-1.7 -0.175,-1.7 -0.325,-1.7 -0.344,-1.696 -0.36,-1.685 -0.371,-1.669 -0.375,-1.65
  body extent -1.5,-1.5 1.5,1.5, height 1
JAE_EDGE_CONN_503480-0400 [mm] "Edge Connector, 0.5mm, 4x1, SMT"
  rect 0.7x2 smd paste-2 mask+0: 1(-1.5,0) 2(-0.5,0) 3(0.5,0) 4(1.5,0)
  silkscreen extent -1.88,-1.97 -1.49,-1.57
M52-5012345 [mm] "CONN RCPT 23POS 0.05 GOLD PCB"
  rect 1.05x1.05 hole 0.7: 1(0,0)
  round 1.05 hole 0.7: 2(1.27,0) 3(2.54,0) 4(3.81,0) 5(5.08,0) 6(6.35,0) 7(7.62,0) 8(8.89,0) 9(10.16,0) 10(11.43,0) 11(12.7,0) 12(13.97,0) 13(15.24,0) 14(16.51,0) 15(17.78,0) 16(19.05,0) 17(20.32,0) 18(21.59,0) 19(22.86,0) 20(24.13,0) 21(25.4,0) 22(26.67,0)
  silkscreen extent -1.6,-1.1 28.78,1.1, body extent -0.3,-0.3 0.3,0.3, height 4.1
RDX0007A-MFG [mm]
  round 1.025 smd paste-1000 mask-1000: 1(-1.312,1.312)
  rrect13% 1.5x2.3 smd paste-1000 mask-1000: 2(-1.15,-0.675) 3(1.15,-0.675)
  round 0.991 smd paste-1000 mask-1000: 4(1.281,1.276)
  rrect45% 0.22x0.6 smd paste+0 mask-1000: 5(0.5,1.9) 6(0,1.9) 7(-0.5,1.9)
  Top Layer region: 1.9,1.8 1.892,1.838 1.871,1.871 1.838,1.892 1.8,1.9 1.8,1.9 0.925,1.9 0.887,1.892 0.854,1.871 0.833,1.838 0.825,1.8 0.825,1.8 0.825,1.634 0.818,1.596 0.796,1.563 0.796,1.563 0.507,1.274 0.474,1.252 0.436,1.245 0.436,1.245 0.39,1.245 0.352,1.237 0.319,1.216 0.298,1.183 0.29,1.145 0.29,1.145 0.29,0.825 0.298,0.787 0.319,0.754 0.352,0.733 0.39,0.725 0.39,0.725 1.8,0.725 1.838,0.733 1.871,0.754 1.892,0.787 1.9,0.825 1.9,0.825
  Top Layer region: -1.9,1.8 -1.887,1.85 -1.85,1.887 -1.8,1.9 -1.8,1.9 -0.925,1.9 -0.887,1.892 -0.854,1.871 -0.833,1.838 -0.825,1.8 -0.825,1.8 -0.825,1.634 -0.818,1.596 -0.796,1.563 -0.796,1.563 -0.507,1.274 -0.474,1.252 -0.436,1.245 -0.436,1.245 -0.39,1.245 -0.34,1.232 -0.303,1.195 -0.29,1.145 -0.29,1.145 -0.29,0.825 -0.298,0.787 -0.319,0.754 -0.352,0.733 -0.39,0.725 -0.39,0.725 -1.8,0.725 -1.838,0.733 -1.871,0.754 -1.892,0.787 -1.9,0.825 -1.9,0.825
  Keep-Out Layer region: -0.2,0.675 0.2,0.675 0.2,1.295 -0.2,1.295
  silkscreen extent -2.07,-2.17 2.07,2.41, body extent -2,-2.1 2,2.3, height 0.25
Samtec_PTT-104-01-x-S [mm] "Header, 2mm, 4x1, TH"
  rect 1.3x1.3 hole 0.81: 1(-3,0)
  round 1.3 hole 0.81: 2(-1,0) 3(1,0) 4(3,0)
  silkscreen extent -3.81,-0.99 3.81,1.3, body extent -4,-0.99 4,0.99, height 4.7

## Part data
C1 C6: library part CMP-0006861-3, "CAP, CERM, 0.1 uF, 50 V, +/- 10%, X7R, 0603", Cap_Case=0603, Manufacturer=Kemet, Supplier Part Number 1=399-5089-1-ND, TempCo=X7R, Tolerance_%=10%, Value1=Unknown, Value2=50V, ValueDisplayed=0.1uF
C2: library part CMP-0008269-1, "CAP, CERM, 22 uF, 16 V, +/- 20%, X6S, 0805", Cap_Case=0805, Manufacturer=MuRata, Supplier Part Number 1=490-9956-1-ND, TempCo=X6S, Tolerance_%=20%, Value1=Unknown, Value2=16V, ValueDisplayed=22uF
C4 C7 C8 C9 C10 C11 C12 C13 C14 C15 C16 C25 C26 C27 C28 C29 C30 C31 C32 C33 C34 C35 C36 C37 C38 C39 C40 C101 C102 C103 C106 C137: library part CMP-0008822-2, "CAP, CERM, 10 uF, 35 V, +/- 10%, X7R, 1206_190", Cap_Case=1206, Manufacturer="Taiyo Yuden", Supplier Part Number 1=587-3007-1-ND, TempCo=X7R, Tolerance_%=10%, Value1=Unknown, Value2=35V, ValueDisplayed=10uF
C5: library part CMP-0007007-5, "CAP, CERM, 10 uF, 25 V, +/- 20%, X5R, 0603", Cap_Case=0603, Manufacturer=TDK, Supplier Part Number 1=445-9015-1-ND, TempCo=X5R, Tolerance_%=20%, Value1="0.004639 ohm", Value2=25V, ValueDisplayed=10uF
C17 C18 C19 C20 C41 C42 C43 C44: library part CMP-0007885-2, "CAP, CERM, 4.7 uF, 35 V, +/- 10%, X7R, 0805", Cap_Case=0805, Manufacturer=TDK, Supplier Part Number 1=445-7555-1-ND, TempCo=X7R, Tolerance_%=10%, Value1="0.002346 ohm", Value2=35V, ValueDisplayed=4.7uF
C21 C22 C23 C24 C45 C46 C47 C48: library part CMP-0006751-4, "CAP, CERM, 100 pF, 25 V, +/- 10%, X7R, 0603", Cap_Case=0603, Manufacturer=Samsung, PartNumber=CL10B101KB8NNNC, Supplier Part Number 1=1276-1909-2-ND, TempCo=X7R, Tolerance_%=10%, Value1=Unknown, Value2=25V, ValueDisplayed=100pF
C49 C50 C55 C56 C60: library part CMP-0007039-5, "CAP, CERM, 0.1 uF, 25 V, +/- 10%, X7R, 0603", Cap_Case=0603, Manufacturer=TDK, Supplier Part Number 1=445-1316-1-ND, TempCo=X7R, Tolerance_%=10%, Value1=Unknown, Value2=25V, ValueDisplayed=0.1uF
C51: library part CMP-0007263-3, "CAP, CERM, 33 pF, 100 V, +/- 5%, C0G/NP0, 0603", Cap_Case=0603, Manufacturer=MuRata, Supplier Part Number 1=490-1339-1-ND, TempCo=C0G/NP0, Tolerance_%=5%, Value1=Unknown, Value2=100V, ValueDisplayed=33pF
C54: library part CMP-0007455-4, "CAP, CERM, 470 pF, 50 V, +/- 10%, X7R, 0603", Cap_Case=0603, Manufacturer=KEMET, Supplier Part Number 1=399-1075-1-ND, TempCo=X7R, Tolerance_%=10%, Value1=Unknown, Value2=50V, ValueDisplayed=470pF
CSTs: library part CMP-0055572-1, "Header, 2mm, 4x1, Gold, TH", Color=Black, Current_A=2.9A, Manufacturer=Samtec
J7: library part Receptacle_23x1, "Receptacle, 23x1, 1.27mm, TH", Manufacturer="Harwin Inc.", Supplier Part Number 1=855-M52-5012345
MP1 MP2 MP3 MP4 MP5 MP6 MP7 MP8 MP9 MP10 MP11 MP12 MP13 MP14 MP15 MP16: "Spacer, SMT, Swage Round, Steel, 2x2mm", PartNumber=2mmx2mmx2mm
P1: library part CMP-0055349-1, "Edge Connector, 0.5 mm, 4x1, SMT", Manufacturer=Molex
Q1 Q2 Q4 Q5 Q7 Q8 Q9 Q10 Q12 Q13 Q15 Q16 Q17 Q18 Q21 Q22 Q23 Q24 Q25 Q26 Q27 Q30 Q31 Q32: library part CMP-0000586-2, "MOSFET, N-CH, 30 V, 100 A, DNK0008A (VSON-CLIP-8)", Alternate Manufacturer=None, Manufacturer="Texas Instruments", Supplier Part Number 1=CSD17573Q5B-ND, Value1=0.0014, Value2="49 nC"
R1: library part CMP-0025782-1, "RES, 30 k, 5%, 0.1 W, 0603", Manufacturer=Vishay-Dale, Power_W=100mW, Supplier Part Number 1=541-30KGCT-ND, TempCo="200 ppm/C", Tolerance_%=5%, Value2=0.1W, Value_Code=30k0, ValueDisplayed=30k
R2: library part CMP-0025753-3, "RES, 20 k, 5%, 0.1 W, 0603", Manufacturer=Vishay-Dale, Power_W=100mW, Supplier Part Number 1=541-20KGCT-ND, TempCo="200 ppm/C", Tolerance_%=5%, Value2=0.1W, Value_Code=20k0, ValueDisplayed=20k
R3: library part CMP-0022917-4, "RES, 220 k, 1%, 0.1 W, 0603", Manufacturer=Yageo, Power_W=100mW, Supplier Part Number 1=311-220KHRCT-ND, TempCo="100 ppm/C", Tolerance_%=1%, Value2=0.1W, Value_Code=220k
R5: library part CMP-0023020-5, "RES, 15.0 k, 1%, 0.1 W, 0603", Manufacturer=Yageo, Power_W=100mW, TempCo="100 ppm/C", Tolerance_%=1%, Value2=0.1W, Value_Code=15k0, ValueDisplayed=15.0k
R23 R118: library part CMP-0023198-5, "RES, 5.10 k, 1%, 0.1 W, 0603", Manufacturer=Yageo, Power_W=100mW, Supplier Part Number 1=311-5.10KHRCT-ND, TempCo="100 ppm/C", Tolerance_%=1%, Value2=0.1W, Value_Code=5k10, ValueDisplayed=5.10k
R26 R29 R56 R89 R92 R94 R97 R105 R108 R117: library part CMP-0015817-2, "RES, 0.0005, 1%, 2 W, 2512", Manufacturer="Stackpole Electronics Inc", Power_W=3W, TempCo=ppm/C, Tolerance_%=1%, Value2=2W, Value_Code=1L000, ValueDisplayed=0.0005
R31 R34 R36 R39 R58 R59: library part CMP-0022711-2, "RES, 1ohm 1%, 0.1 W, 0603", Manufacturer=Panasonic, Power_W=100mW, TempCo="200 ppm/C", Tolerance_%=1%, Value2=0.1W, Value_Code=1R, ValueDisplayed=1R0
R42 R44 R47 R49 R67 R86 R87 R88 R98 R119: library part CMP-0022736-4, "RES, 100, 1%, 0.1 W, 0603", Manufacturer=Yageo, Power_W=100mW, Supplier Part Number 1=311-100HRCT-ND, TempCo="100 ppm/C", Tolerance_%=1%, Value2=0.1W, Value_Code=100R, ValueDisplayed=100
R62 R63: library part CMP-0022711-2, "RES, 1.0, 1%, 0.1 W, 0603", Manufacturer=Panasonic, PartNumber=ERJ-3RQF2R2V, Power_W=100mW, Supplier Part Number 1=P2.2AJCT-ND, TempCo="200 ppm/C", Tolerance_%=1%, Value2=0.1W, Value_Code=2R20, ValueDisplayed=1R0
R96: library part CMP-0022906-5, "RES, 20.0 k, 1%, 0.1 W, 0603", Manufacturer=Yageo, Power_W=100mW, Supplier Part Number 1=311-20.0KHRCT-ND, TempCo="100 ppm/C", Tolerance_%=1%, Value2=0.1W, Value_Code=20k0, ValueDisplayed=20.0k
TRAN1 TRAN2: library part Transformer_sec, "PQ32 TRANSFORMER", Manufacturer="YAXIN ELECTRONIC TECH"
U1: library part CMP-0097277-1, "3V to 16 V Input, 3-A Synchronous Step-Down Voltage Regulator Module, QFN-FCMOD7", Manufacturer="Texas Instruments", Max Supply Voltage=16V, Min Supply Voltage=3V, Nominal Supply Current=120-400uA, Operating Temperature Range="-40°C to +125°C", Output Voltage=0.6-7V, Switching Frequency=1400/2000kHz
U2 U3 U4 U10: library part CMP-0013393-6, "120-V, 3-A Peak, 5-V UVLO, 3x3, High-Frequency, High-Side/Low-Side Driver, DRC0010J (VSON-10)", Manufacturer="Texas Instruments", Rating=Catalog
U5 U6: library part CMP-0075733-4, "26-V, Bi-Directional, Zero-Drift, High Accuracy, Low-/High-Side, Voltage Out Current Shunt Monitor, DCK0006A (SOT-SC70-6)", Alternate Manufacturer="Texas Instruments", Alternate PartNumber=INA210BIDCKT, Operating Temperature Range="-40 to 125 C", Rating=Catalog
U20: library part CMP-0043733-1, "Low-Power Single Operational Amplifier, 3 to 30 V, -40 to 125 degC, 5-pin SOT23 (DBV5), Green (RoHS & no Sb/Br)", Manufacturer="Texas Instruments", Total Supply Voltage(Max)(+5V is 5, +/-5V is 10)=30, Total Supply Voltage(Min)(+5V is 5, +/-5V is 10)=3

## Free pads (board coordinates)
  oval 5x2 hole 1 slot 4 at 0 deg: 4(65.9,9)
  oval 4x2 hole 1 slot 3 at 0 deg: 4(66.963,48.6)
  oval 4x5 hole 3: 4(67.7,36.1) 5(67.8,22.9)
  oval 2x4 hole 1 slot 3 at 90 deg: 4(68.481,11.6) 4(68.7,46.4)

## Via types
v1: diameter 0.508, hole 0.254, Top Layer to Bottom Layer, tented both sides, 996 vias
v2: diameter 0.508, hole 0.254, Layer 2 to Bottom Layer, tented both sides, 151 vias
v3: diameter 0.508, hole 0.254, Top Layer to Bottom Layer, 14 vias
v4: diameter 0.5, hole 0.2, Top Layer to Bottom Layer, 12 vias
v5: diameter 0.762, hole 0.356, Top Layer to Bottom Layer, tented both sides, 1 vias

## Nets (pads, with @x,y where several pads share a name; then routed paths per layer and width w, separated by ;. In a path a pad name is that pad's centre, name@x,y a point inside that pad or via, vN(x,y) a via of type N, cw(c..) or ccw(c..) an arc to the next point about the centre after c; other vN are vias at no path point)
12Vo_A: C4.1 C7.1 C8.1 C9.1 C10.1 C11.1 C12.1 C13.1 C14.1 C15.1 C16.1 C101.1 C102.1 C103.1 C106.1 C137.1 MP1.1 MP2.1 MP3.1 MP4.1 MP5.1 MP6.1 Q1.5 Q1.6 Q1.7 Q1.8 Q1.9@25.196,34.826 Q2.5 Q2.6 Q2.7 Q2.8 Q2.9@53.086,41.04 Q4.5 Q4.6 Q4.7 Q4.8 Q4.9@53.086,46.68 Q5.5 Q5.6 Q5.7 Q5.8 Q5.9@25.196,46.373 Q7.5 Q7.6 Q7.7 Q7.8 Q7.9@25.196,40.6 Q8.5 Q8.6 Q8.7 Q8.8 Q8.9@53.086,35.401 R26.2 R29.2 R89.2 R92.2 R108.2 U5.4 | length 12.6
  Top Layer w0.254: R29.2@57.553,39.973 60.024,39.973 60.173,39.824 60.173,31.275 59.601,30.703 59.112,30.703 U5.4@59.043,30.634
  other v1: 23.678,29.794 24.178,29.794 24.678,29.794 25.178,29.794 25.678,29.794 26.178,29.794 26.678,29.794 27.178,29.794 23.678,30.294 24.178,30.294 24.678,30.294 25.178,30.294 25.678,30.294 26.178,30.294 26.678,30.294 27.178,30.294 23.678,30.794 24.178,30.794 24.678,30.794 25.178,30.794 25.678,30.794 26.178,30.794 26.678,30.794 27.178,30.794 23.678,31.294 24.178,31.294 24.678,31.294 25.178,31.294 25.678,31.294 26.178,31.294 26.678,31.294 27.178,31.294 58.315,31.747 58.823,31.747 59.331,31.747 23.678,31.794 24.178,31.794 24.678,31.794 25.178,31.794 25.678,31.794 26.178,31.794 26.678,31.794 27.178,31.794 23.678,32.294 24.178,32.294 24.678,32.294 25.178,32.294 25.678,32.294 26.178,32.294 26.678,32.294 27.178,32.294 23.678,32.794 24.178,32.794 24.678,32.794 25.178,32.794 25.678,32.794 26.178,32.794 26.678,32.794 27.178,32.794 58.315,33.004 58.823,33.004 59.331,33.004 23.678,33.294 24.178,33.294 24.678,33.294 25.178,33.294 25.678,33.294 26.178,33.294 26.678,33.294 27.178,33.294 23.678,33.794 24.178,33.794 24.678,33.794 25.178,33.794 25.678,33.794 26.178,33.794 26.678,33.794 27.178,33.794 58.315,34.261 58.823,34.261 59.331,34.261 23.678,34.294 24.178,34.294 24.678,34.294 25.178,34.294 25.678,34.294 26.178,34.294 26.678,34.294 27.178,34.294 23.678,34.794 24.178,34.794 24.678,34.794 25.178,34.794 25.678,34.794 26.178,34.794 26.678,34.794 27.178,34.794 23.678,35.294 24.178,35.294 24.678,35.294 25.178,35.294 25.678,35.294 26.178,35.294 26.678,35.294 27.178,35.294 58.315,35.519 58.823,35.519 59.331,35.519 23.678,35.794 24.178,35.794 24.678,35.794 25.178,35.794 25.678,35.794 26.178,35.794 26.678,35.794 27.178,35.794 23.678,36.294 24.178,36.294 24.678,36.294 25.178,36.294 25.678,36.294 26.178,36.294 26.678,36.294 27.178,36.294 58.315,36.776 58.823,36.776 59.331,36.776 23.678,36.794 24.178,36.794 24.678,36.794 25.178,36.794 25.678,36.794 26.178,36.794 26.678,36.794 27.178,36.794 23.678,37.294 24.178,37.294 24.678,37.294 25.178,37.294 25.678,37.294 26.178,37.294 26.678,37.294 27.178,37.294 23.678,37.794 24.178,37.794 24.678,37.794 25.178,37.794 25.678,37.794 26.178,37.794 26.678,37.794 27.178,37.794 58.315,38.034 58.823,38.034 59.331,38.034 23.678,38.294 24.178,38.294 24.678,38.294 25.178,38.294 25.678,38.294 26.178,38.294 26.678,38.294 27.178,38.294 23.678,38.794 24.178,38.794 24.678,38.794 25.178,38.794 25.678,38.794 26.178,38.794 26.678,38.794 27.178,38.794 23.678,39.294 24.178,39.294 24.678,39.294 25.178,39.294 25.678,39.294 26.178,39.294 26.678,39.294 27.178,39.294 58.315,39.291 58.823,39.291 59.331,39.291 23.678,39.794 24.178,39.794 24.678,39.794 25.178,39.794 25.678,39.794 26.178,39.794 26.678,39.794 27.178,39.794 23.678,40.294 24.178,40.294 24.678,40.294 25.178,40.294 25.678,40.294 26.178,40.294 26.678,40.294 27.178,40.294 23.678,40.794 24.178,40.794 24.678,40.794 25.178,40.794 25.678,40.794 26.178,40.794 26.678,40.794 27.178,40.794 58.315,40.85 58.823,40.85 59.331,40.85 23.678,41.294 24.178,41.294 24.678,41.294 25.178,41.294 25.678,41.294 26.178,41.294 26.678,41.294 27.178,41.294 23.678,41.794 24.178,41.794 24.678,41.794 25.178,41.794 25.678,41.794 26.178,41.794 26.678,41.794 27.178,41.794 58.315,42.108 58.823,42.108 59.331,42.108 23.678,42.294 24.178,42.294 24.678,42.294 25.178,42.294 25.678,42.294 26.178,42.294 26.678,42.294 27.178,42.294 23.678,42.794 24.178,42.794 24.678,42.794 25.178,42.794 25.678,42.794 26.178,42.794 26.678,42.794 27.178,42.794 23.678,43.294 24.178,43.294 24.678,43.294 25.178,43.294 25.678,43.294 26.178,43.294 26.678,43.294 27.178,43.294 58.315,43.365 58.823,43.365 59.331,43.365 23.678,43.794 24.178,43.794 24.678,43.794 25.178,43.794 25.678,43.794 26.178,43.794 26.678,43.794 27.178,43.794 23.678,44.294 24.178,44.294 24.678,44.294 25.178,44.294 25.678,44.294 26.178,44.294 26.678,44.294 27.178,44.294 58.315,44.623 58.823,44.623 59.331,44.623 23.678,44.794 24.178,44.794 24.678,44.794 25.178,44.794 25.678,44.794 26.178,44.794 26.678,44.794 27.178,44.794 23.678,45.294 24.178,45.294 24.678,45.294 25.178,45.294 25.678,45.294 26.178,45.294 26.678,45.294 27.178,45.294 23.678,45.794 24.178,45.794 24.678,45.794 25.178,45.794 25.678,45.794 26.178,45.794 26.678,45.794 27.178,45.794 58.315,45.88 58.823,45.88 59.331,45.88 23.678,46.294 24.178,46.294 24.678,46.294 25.178,46.294 25.678,46.294 26.178,46.294 26.678,46.294 27.178,46.294 23.678,46.794 24.178,46.794 24.678,46.794 25.178,46.794 25.678,46.794 26.178,46.794 26.678,46.794 27.178,46.794 58.315,47.137 58.823,47.137 59.331,47.137 23.678,47.294 24.178,47.294 24.678,47.294 25.178,47.294 25.678,47.294 26.178,47.294 26.678,47.294 27.178,47.294 23.678,47.794 24.178,47.794 24.678,47.794 25.178,47.794 25.678,47.794 26.178,47.794 26.678,47.794 27.178,47.794 23.678,48.294 24.178,48.294 24.678,48.294 25.178,48.294 25.678,48.294 26.178,48.294 26.678,48.294 27.178,48.294 58.315,48.395 58.823,48.395 59.331,48.395 23.678,48.794 24.178,48.794 24.678,48.794 25.178,48.794 25.678,48.794 26.178,48.794 26.678,48.794 27.178,48.794 23.678,49.294 24.178,49.294 24.678,49.294 25.178,49.294 25.678,49.294 26.178,49.294 26.678,49.294 27.178,49.294
  other v2: 36.126,33.321 36.634,33.321 36.126,34.578 36.634,34.578 36.126,35.836 36.634,35.836 36.126,37.093 36.634,37.093 36.126,38.351 36.634,38.351 36.126,39.608 36.634,39.608 36.126,40.734 36.634,40.734 36.126,41.991 36.634,41.991 36.126,43.248 36.634,43.248 36.126,44.506 36.634,44.506 36.126,45.763 36.634,45.763 36.126,47.021 36.634,47.021 36.126,48.278 36.634,48.278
